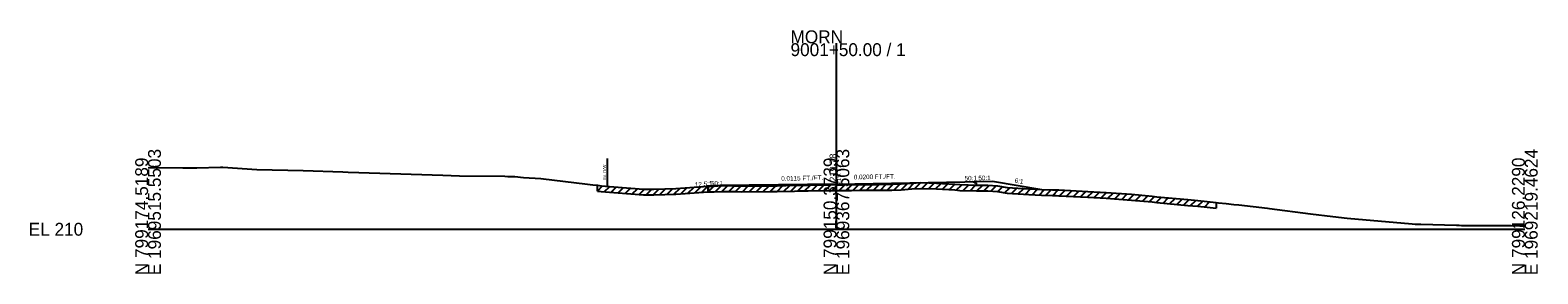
# Model space of a CAD drawing. Extents: x -26 to 2313, y -1511 to 5559.
# Drawn here: x -25.7 to 302.8, y -9.7 to 43.3 of the extents above; entities that cross this region are included whole.
import ezdxf

# ---------------------------------------------------------------- set-up
doc = ezdxf.new("R2010")
doc.units = 0
for name, color, linetype in [('Default', 7, 'Continuous'), ('RD_XS_Base', 7, 'Continuous'), ('RD_XS_EarthShd', 7, 'Continuous'), ('RD_XS_ExGround', 7, 'Continuous'), ('RD_XS_ExPaveRet', 7, 'Continuous'), ('RD_XS_ExRW', 7, 'Continuous'), ('RD_XS_Misc_Line', 7, 'Continuous'), ('RD_XS_Pave', 7, 'Continuous'), ('RD_XS_PaveShd', 7, 'Continuous'), ('RD_XS_TieSlope', 7, 'Continuous'), ('RD_XS_TX_Elev_EX', 7, 'Continuous'), ('RD_XS_TX_Elev_PR', 7, 'Continuous'), ('RD_XS_TX_Profile', 7, 'Continuous'), ('RD_XS_TX_ShdSlope', 7, 'Continuous'), ('RD_XS_TX_Slope', 7, 'Continuous')]:
    doc.layers.add(name, color=color, linetype=linetype)

msp = doc.modelspace()

# ---------------------------------------------------------------- linework, layer by layer
at = {"layer": 'Default'}
for p, q in [((150, 0), (150, 40.48)), ((0, 0), (150, 0)), ((150, 0), (300, 0))]:
    msp.add_line(p, q, dxfattribs=at)
at = {"layer": 'RD_XS_Base'}
for p, q in [((180, 10.08), (180, 10.38)), ((180.5, 10.09), (180, 10.08)), ((180.5, 9.61), (180.5, 10.09)), ((122.7, 9.4), (122.7, 9.45)), ((180.12, 9.6), (180.5, 9.61))]:
    msp.add_line(p, q, dxfattribs=at)
at = {"layer": 'RD_XS_EarthShd'}
for p, q in [((180, 10.38), (184, 10.46)), ((122.7, 9.45), (121.73, 9.37))]:
    msp.add_line(p, q, dxfattribs=at)
at = {"layer": 'RD_XS_ExGround'}
msp.add_lwpolyline([(0, 13.42), (7.59, 13.35), (7.92, 13.35), (10.63, 13.34), (15.76, 13.49), (16.32, 13.48), (23.67, 13.02), (33.81, 12.79), (42.46, 12.51), (43.63, 12.46), (64.25, 11.77), (67.88, 11.62), (77.71, 11.55), (78.36, 11.5), (79.94, 11.48), (81.82, 11.28), (85.61, 11.06), (95.75, 9.83), (96.9, 9.69), (97.9, 9.56), (98.73, 9.48), (107.95, 8.73), (110.23, 8.76), (114.97, 8.9), (122.03, 9.39), (123.38, 9.41), (125.03, 9.49), (127.84, 9.46), (129.22, 9.43), (135.87, 9.46), (136.79, 9.47), (137.11, 9.48), (140.87, 9.57), (141.82, 9.59), (143.21, 9.61), (143.84, 9.61), (148.33, 9.7), (149.45, 9.72), (150.25, 9.71), (153.27, 9.69), (155.16, 9.73), (155.81, 9.75), (156.61, 9.75), (159.14, 9.76), (162.1, 9.79), (164.09, 9.85), (166.42, 10.05), (168.38, 10.15), (171.84, 10.03), (175.77, 9.8), (176.88, 9.72), (180.54, 9.58), (183.02, 9.6), (185.06, 9.44), (187.2, 9.08), (191.95, 8.79), (194.69, 8.66), (197.1, 8.61), (197.9, 8.59), (198.43, 8.56), (204.79, 8.22), (208.78, 8.01), (214.31, 7.61), (218.83, 7.19), (219.78, 7.09), (226.57, 6.45), (228.73, 6.24), (230.79, 6.03), (232.76, 5.81), (233.24, 5.76), (234.93, 5.58), (236.61, 5.41), (237.7, 5.3), (243.96, 4.58), (244.37, 4.53), (253.28, 3.35), (258.18, 2.75), (261.32, 2.41), (275.42, 1.17), (276.11, 1.14), (277.36, 1.09), (285.12, 0.89), (285.67, 0.86), (286.18, 0.85), (295.71, 0.83), (297, 0.8), (298.94, 0.75), (300, 0.72)], dxfattribs=at)
at = {"layer": 'RD_XS_ExPaveRet'}
for p, q in [((97.9, 8.31), (97.9, 9.56)), ((97.9, 8.31), (98.73, 8.23)), ((98.73, 8.23), (107.95, 7.48)), ((107.95, 7.48), (110.23, 7.51)), ((110.23, 7.51), (114.97, 7.65)), ((114.97, 7.65), (122.03, 8.14)), ((122.03, 9.39), (122.03, 8.14)), ((122.03, 8.14), (122.03, 9.39)), ((122.03, 8.14), (123.38, 8.16)), ((123.38, 8.16), (125.03, 8.24)), ((125.03, 8.24), (127.84, 8.21)), ((127.84, 8.21), (129.22, 8.18)), ((129.22, 8.18), (135.87, 8.21)), ((135.87, 8.21), (136.79, 8.22)), ((136.79, 8.22), (137.11, 8.23)), ((137.11, 8.23), (140.87, 8.32)), ((140.87, 8.32), (141.82, 8.34)), ((141.82, 8.34), (143.21, 8.36)), ((143.21, 8.36), (143.84, 8.36)), ((143.84, 8.36), (148.33, 8.45)), ((148.33, 8.45), (149.45, 8.47)), ((149.45, 8.47), (150.25, 8.46)), ((150.25, 8.46), (153.27, 8.44)), ((153.27, 8.44), (155.16, 8.48)), ((155.16, 8.48), (155.81, 8.5)), ((155.81, 8.5), (156.61, 8.5)), ((156.61, 8.5), (159.14, 8.51)), ((159.14, 8.51), (162.1, 8.54)), ((162.1, 8.54), (164.09, 8.6)), ((164.09, 8.6), (166.42, 8.8)), ((166.42, 8.8), (168.38, 8.9)), ((168.38, 8.9), (171.84, 8.78)), ((171.84, 8.78), (175.77, 8.55)), ((175.77, 8.55), (176.88, 8.47)), ((176.88, 8.47), (180.54, 8.33)), ((180.54, 8.33), (183.02, 8.35)), ((183.02, 8.35), (185.06, 8.19)), ((185.06, 8.19), (187.2, 7.83)), ((187.2, 7.83), (191.95, 7.54)), ((191.95, 7.54), (194.69, 7.41)), ((194.69, 7.41), (197.1, 7.36)), ((197.1, 7.36), (197.9, 7.34)), ((197.9, 7.34), (198.43, 7.31)), ((198.43, 7.31), (204.79, 6.97)), ((204.79, 6.97), (208.78, 6.76)), ((208.78, 6.76), (214.31, 6.36)), ((214.31, 6.36), (218.83, 5.94)), ((218.83, 5.94), (219.78, 5.84)), ((219.78, 5.84), (226.57, 5.2)), ((226.57, 5.2), (228.73, 4.99)), ((228.73, 4.99), (230.79, 4.78)), ((230.79, 4.78), (232.76, 4.56)), ((232.76, 5.81), (232.76, 4.56))]:
    msp.add_line(p, q, dxfattribs=at)
at = {"layer": 'RD_XS_ExRW'}
msp.add_line((100.05, 15.38), (100.05, 9.38), dxfattribs=at)
at = {"layer": 'RD_XS_Misc_Line'}
for p, q in [((164.09, 8.6), (165.46, 9.97)), ((165.6, 8.73), (166.94, 10.08)), ((167.1, 8.84), (168.41, 10.15)), ((168.6, 8.89), (169.81, 10.1)), ((170.1, 8.84), (171.31, 10.05)), ((171.6, 8.79), (172.79, 9.97)), ((173.11, 8.7), (174.29, 9.89)), ((97.9, 8.31), (99.06, 9.46)), ((99.42, 8.18), (100.59, 9.33)), ((100.94, 8.05), (102.1, 9.21)), ((102.45, 7.93), (103.62, 9.08)), ((103.97, 7.8), (105.14, 8.96)), ((105.49, 7.68), (106.65, 8.83)), ((107, 7.55), (108.19, 8.73)), ((108.52, 7.48), (109.8, 8.75)), ((110.04, 7.5), (111.34, 8.79)), ((111.55, 7.55), (112.86, 8.84)), ((113.07, 7.59), (114.37, 8.88)), ((114.59, 7.64), (115.93, 8.97)), ((116.1, 7.73), (117.46, 9.07)), ((117.62, 7.83), (118.98, 9.18)), ((119.14, 7.94), (120.5, 9.28)), ((120.65, 8.04), (122.01, 9.39)), ((122.03, 8.14), (123.3, 9.41)), ((123.54, 8.17), (124.85, 9.48)), ((125.04, 8.24), (126.28, 9.47)), ((126.54, 8.22), (127.78, 9.46)), ((128.04, 8.2), (129.27, 9.43)), ((129.54, 8.18), (130.8, 9.44)), ((131.05, 8.19), (132.3, 9.45)), ((132.55, 8.2), (133.81, 9.45)), ((134.05, 8.21), (135.31, 9.46)), ((135.55, 8.21), (136.82, 9.47)), ((137.06, 8.23), (138.34, 9.51)), ((138.56, 8.26), (139.84, 9.55)), ((140.06, 8.3), (141.34, 9.58)), ((141.56, 8.33), (142.83, 9.6)), ((143.06, 8.35), (144.33, 9.62)), ((144.57, 8.38), (145.84, 9.65)), ((146.07, 8.41), (147.34, 9.68)), ((147.57, 8.43), (148.84, 9.71)), ((149.07, 8.46), (150.33, 9.71)), ((150.57, 8.46), (151.82, 9.7)), ((152.08, 8.45), (153.32, 9.69)), ((153.58, 8.45), (154.86, 9.73)), ((155.08, 8.48), (156.36, 9.75)), ((156.58, 8.5), (157.84, 9.75)), ((158.09, 8.5), (159.34, 9.76)), ((159.59, 8.51), (160.86, 9.78)), ((161.09, 8.53), (162.36, 9.8)), ((162.59, 8.56), (163.88, 9.85)), ((174.61, 8.62), (175.79, 9.8)), ((176.11, 8.53), (177.29, 9.7)), ((177.61, 8.44), (178.82, 9.65)), ((179.12, 8.39), (180.32, 9.59)), ((180.62, 8.33), (181.88, 9.59)), ((182.12, 8.35), (183.35, 9.58)), ((183.62, 8.31), (184.78, 9.47)), ((185.12, 8.18), (186.19, 9.25)), ((186.63, 7.93), (187.75, 9.05)), ((188.13, 7.77), (189.31, 8.95)), ((189.63, 7.68), (190.81, 8.86)), ((191.13, 7.59), (192.32, 8.77)), ((192.63, 7.51), (193.83, 8.7)), ((194.14, 7.44), (195.35, 8.65)), ((195.64, 7.39), (196.87, 8.62)), ((197.14, 7.36), (198.35, 8.57)), ((198.64, 7.3), (199.83, 8.49)), ((200.15, 7.22), (201.33, 8.41)), ((201.65, 7.14), (202.83, 8.32)), ((203.15, 7.06), (204.34, 8.24)), ((204.65, 6.98), (205.84, 8.16)), ((206.15, 6.9), (207.34, 8.08)), ((207.66, 6.82), (208.84, 8)), ((209.16, 6.73), (210.33, 7.89)), ((210.66, 6.62), (211.83, 7.78)), ((212.16, 6.51), (213.33, 7.68)), ((213.66, 6.4), (214.82, 7.56)), ((215.17, 6.28), (216.31, 7.42)), ((216.67, 6.14), (217.82, 7.28)), ((218.17, 6), (219.31, 7.14)), ((219.67, 5.85), (220.82, 6.99)), ((221.18, 5.71), (222.32, 6.85)), ((222.68, 5.57), (223.82, 6.71)), ((224.18, 5.42), (225.32, 6.57)), ((225.68, 5.28), (226.82, 6.42)), ((227.18, 5.14), (228.32, 6.28)), ((228.69, 4.99), (229.82, 6.13)), ((230.19, 4.84), (231.32, 5.97))]:
    msp.add_line(p, q, dxfattribs=at)
at = {"layer": 'RD_XS_Pave'}
for q in [(178, 10.34), (124.7, 9.49)]:
    msp.add_line((150, 9.78), q, dxfattribs=at)
at = {"layer": 'RD_XS_PaveShd'}
for p, q in [((178, 10.34), (180, 10.38)), ((124.7, 9.49), (122.7, 9.45))]:
    msp.add_line(p, q, dxfattribs=at)
at = {"layer": 'RD_XS_TieSlope'}
msp.add_line((184, 10.46), (194.79, 8.66), dxfattribs=at)

# ---------------------------------------------------------------- texts
at = {"layer": 'Default'}
for s, p in [('MORN', (140, 40.48)), ('9001+50.00 / 1', (140, 37.68)), ('EL 210', (-26, -1.4))]:
    msp.add_text(s, height=2.8, dxfattribs=at).set_placement(p)
for s, p in [('E 1969515.5503', (2.8, -10)), ('E 1969367.5063', (152.8, -10)), ('E 1969219.4624', (302.8, -10)), ('N 799174.5189', (0, -10)), ('N 799150.3739', (150, -10)), ('N 799126.2290', (300, -10))]:
    msp.add_text(s, height=2.8, rotation=90, dxfattribs=at).set_placement(p)
at = {"layer": 'RD_XS_ExRW'}
msp.add_text('Ex. R/W ', height=0.65, rotation=90, dxfattribs=at).set_placement((99.8, 10.76))
at = {"layer": 'RD_XS_TX_Elev_EX'}
msp.add_text('219.71', height=1, rotation=90, dxfattribs=at).set_placement((151.01, 9.71))
at = {"layer": 'RD_XS_TX_Elev_PR'}
msp.add_text(' 219.78', height=1.5, rotation=90, dxfattribs=at).set_placement((150, 9.78))
at = {"layer": 'RD_XS_TX_Profile'}
for rotation, p in [(1.1455, (122.64, 9.48)), (1.1458, (177.94, 10.59))]:
    msp.add_text('50:1', height=1, rotation=rotation, dxfattribs=at).set_placement(p)
at = {"layer": 'RD_XS_TX_ShdSlope'}
for s, rotation, p in [('12.5:1', 4.5728, (119.2, 9.2)), ('50:1', 1.1458, (180.94, 10.65))]:
    msp.add_text(s, height=1, rotation=rotation, dxfattribs=at).set_placement(p)
at = {"layer": 'RD_XS_TX_Slope'}
for s, rotation, p in [('0.0115 FT./FT.', 1.1455, (137.98, 10.54)), ('0.0200 FT./FT.', 1.1458, (153.79, 10.85)), ('6:1', 350.5377, (188.78, 10.17))]:
    msp.add_text(s, height=1, rotation=rotation, dxfattribs=at).set_placement(p)

doc.saveas('drawing.dxf')
